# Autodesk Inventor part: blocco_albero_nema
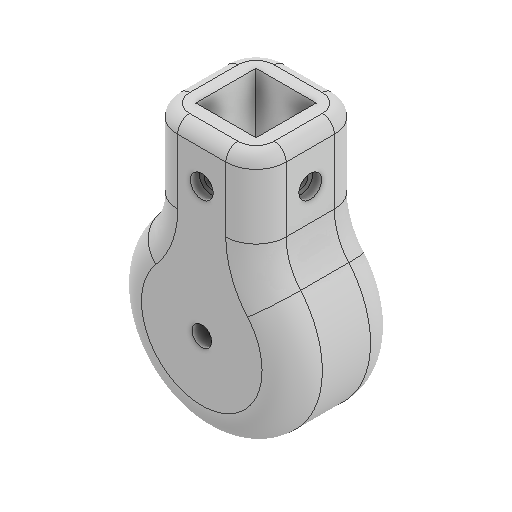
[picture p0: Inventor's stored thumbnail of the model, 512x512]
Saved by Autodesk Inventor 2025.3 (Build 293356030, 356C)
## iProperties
Created: 2026-03
Part Number: blocco_albero_nema
Material: Generico
Document SubType Name: Modeling
Designer: R5800u
Density: 1 g/cm^3
Appearance: Default
Author: R5800u
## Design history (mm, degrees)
sketch "Schizzo1"
  geometry: L1 (-2.646, 3)-(2.646, 3); L2 (0, 0)-(0, 30); L3 (-18, 24)-(18, 24); L4 (18, 24)-(18, 58); L5 (18, 58)-(-18, 58); L6 (-18, 58)-(-18, 24); A1 r 30 centre (0, 0) between (0, 30) and (-18, 24); A2 r 4 centre (0, 0) between (-2.646, 3) and (2.646, 3); 2 further points
  constraints: 12 end point, 4 point on circle, 2 centre point, 2 coincident, 2 horizontal, 2 parallel, 1 perpendicular, 1 vertical, 1 other
  dimensions: "d0" = 60 diameter of A1; "d1" = 8 diameter of A2; "d2" = 3 distance from line of point (0, 0) L1; "d5" = 36 distance of L4.end L5.end; "d6" = 34 distance of L3.end L4.end
extrude "Estrusione1" new body sketch "Schizzo1" stored distance "d3" = 36; taper "d4" = 0 deg
sketch "Schizzo2"
  geometry: L1 (8, -28)-(28, -28); L2 (28, -28)-(28, -8); L3 (28, -8)-(8, -8); L4 (8, -8)-(8, -28); L5 (8, -28)-(28, -8); L6 (28, -28)-(8, -8); 2 further points
  constraints: 12 end point, 2 midpoint, 2 parallel, 1 horizontal, 1 perpendicular
  dimensions: "d7" = 20 distance of L3.end L2.end; "d8" = 20 distance of L2.end L1.end
extrude "Estrusione2" cut sketch "Schizzo2" distance "d9" = 30; taper "d10" = 0 deg
fillet "Raccordo1" dims "d11" = 20
fillet "Raccordo2" dims "d12" = 10
fillet "Raccordo3" dims "d13" = 4
sketch "Schizzo3"
  geometry: C1 r 4 at (0, 0); A1 r 4 centre (0, 0) between (-2.646, 3) and (2.646, 3) reference; 3 further points
  constraints: 1 centre point, 1 coincident
node "Piano di lavoro1"
extrude "Estrusione3" join sketch "Schizzo3" stored distance "d14" = 10; taper "d15" = 0 deg
sketch "Schizzo4"
  geometry: L1 (-8, 54)-(8, 54) reference; L2 (-8, 32.496)-(-8, 54) reference; L3 (8, 54)-(8, 32.496) reference; A1 r 30 centre (-38, 32.496) between (-15.2, 12.998) and (-8, 32.496) reference; A2 r 20 centre (0, 0) between (-15.2, 12.998) and (15.2, 12.998) reference; A3 r 30 centre (38, 32.496) between (8, 32.496) and (15.2, 12.998) reference; 1 further point
hole "Foro1" sketch "Schizzo4" at (0, 0) diameter "d16" = 3.2; stored, may be unused: countersink angle "d20" = 90 deg, drill point angle "d22" = 118 deg; dims "d17" = 6, "d18" = 6.5, "d19" = 10, "d21" = 8
sketch "Schizzo5"
  geometry: L1 (0, 25.504)-(16, 25.504) reference; L2 (8, 25.504)-(8, 10.504); 1 further point
  constraints: 2 end point, 1 midpoint, 1 vertical
  dimensions: "d23" = 15 distance of L2.start L2.end
hole "Foro2" sketch "Schizzo5" at (8, 10.504) diameter "d24" = 4.3; stored, may be unused: countersink angle "d28" = 90 deg, drill point angle "d30" = 118 deg; dims "d25" = 6, "d26" = 7.5, "d27" = 3, "d29" = 8
pattern_circular "Serie circolare1" dims angle "d39" = 360 deg
node "Solido1"
node "Linea chiusa proiettata1"
